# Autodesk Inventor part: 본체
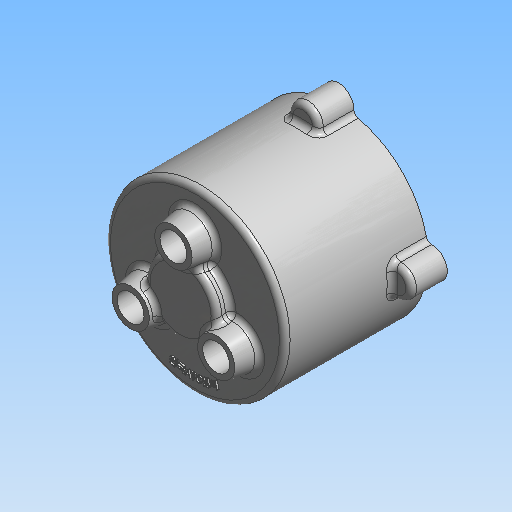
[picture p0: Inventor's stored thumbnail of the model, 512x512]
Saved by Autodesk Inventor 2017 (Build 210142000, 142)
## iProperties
Created: 2021-07
Part Number: 본체
Document SubType Name: 모델링
Designer: mdu
Material: 알루미늄 6061
Density: 2.71 g/cm^3
Mass: 473.469 g
Surface Area: 688.944 cm^2
Volume: 174.712 cm^3
Appearance: 알루미늄 - 평지
변환 표준: STEP AP214IS
파일 이름: C:\Users\SeoGD\Desktop\?쒗뿕\紐몄껜.stp
전처리기: Build: 253, Release: 2010 SP1 - Date: Wed 07/29/2009
전송 단위: 밀리미터
불확실성: 0.01
Author: mdu
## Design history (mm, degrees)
sketch "스케치2"
  geometry: C1 r 50 at (0, 0); 1 further point
  constraints: 1 centre point, 1 coincident
  dimensions: "d9" = 100 diameter of C1
extrude "돌출2" new body sketch "스케치2" distance "d10" = 80; taper "d11" = 0 deg
feature "쉘1" dims "d12" = 5
sketch "스케치3" dims "d13" = 55
  geometry: C1 r 7.5 at (0, 27.5); C2 r 12.5 at (0, 27.5); 2 further points
  constraints: 2 centre point, 2 coincident, 2 vertical alignment, 2 other
  dimensions: "d14" = 15 diameter of C1; "d15" = 25 diameter of C2
extrude "돌출3" join sketch "스케치3" distance "d16" = 12; taper "d17" = -10 deg
sketch "스케치4"
  geometry: L1 (0, 0)-(0, 88); L2 (0, 70)-(14, 70); L3 (-45, 75)-(45, 75) reference; L4 (-50, 80)-(50, 80) reference; L5 (14, 70)-(14, 75); L6 (20, 80)-(20, 88); L7 (20, 88)-(0, 88); L8 (20, 80)-(14, 75)
  constraints: 12 end point, 3 point on line, 2 perpendicular, 1 vertical
  dimensions: "d34" = 40 diameter of L6 L1; "d35" = 90 deg angle of L5 L3; "d36" = 5 distance between parallel lines of L2 L3; "d37" = 8 distance between parallel lines of L7 L4; "d51" = 28 diameter of L5.end L1
revolve "회전1" sketch "스케치4" stored, may be unused: angle "d38" = 90 deg
hole "구멍3" diameter "d41" = 15; stored, may be unused: countersink angle "d45" = 90 deg, drill point angle "d47" = 0 deg; dims "d39" = 10, "d40" = 10, "d42" = 6, "d43" = 22, "d44" = 13, "d46" = 15
chamfer "모따기2" distance "d48" = 1; stored, may be unused: second distance "d49" = 2, angle "d50" = 45 deg
fillet "모깎기4" dims "d78" = 3
hole "구멍2" diameter "d20" = 15; stored, may be unused: countersink angle "d24" = 90 deg, drill point angle "d26" = 118 deg; dims "d21" = 6, "d22" = 25, "d23" = 1, "d25" = 15, "d76" = 10, "d77" = 10
chamfer "모따기1" distance "d27" = 1; stored, may be unused: second distance "d28" = 2, angle "d29" = 45 deg
sketch "스케치9"
  geometry: C1 r 12.5 at (0, 0) reference; C2 r 12.5 at (-23.816, -41.25) reference; C3 r 12.5 at (23.816, -41.25) reference; 1 further point
extrude "돌출5" cut sketch "스케치9" stored distance "d79" = 10; taper "d80" = 0 deg
fillet "모깎기1" dims "d52" = 3
fillet "모깎기2" dims "d53" = 3, "d72" = 0.2
sketch "스케치5"
  geometry: A1 r 50 centre (0, 0) between (50, 0) and (-8.074, 49.344) reference; A2 r 8.5 centre (0, 52) between (8.074, 49.344) and (-8.074, 49.344); 1 further point
  constraints: 5 point on circle, 1 centre point, 1 horizontal alignment
  dimensions: "d54" = 90 deg dimension on point (0, 0) A2.centre A1.start; "d55" = 52 distance of A2.centre point (0, 0); "d56" = 17 diameter of A2
extrude "돌출4" join sketch "스케치5" distance "d57" = 20; taper "d58" = 0 deg
fillet "모깎기3" dims "d59" = 3
hole "구멍4" diameter "d62" = 4.134; stored, may be unused: countersink angle "d66" = 90 deg, drill point angle "d68" = 118 deg; dims "d60" = 10, "d61" = 10, "d63" = 12, "d64" = 22, "d65" = 13, "d67" = 15
sketch "스케치6"
  geometry: C1 r 47 at (0, 0) reference; C2 r 42.5 at (0, 0); 1 further point
  constraints: 1 centre point, 1 coincident, 1 other
  dimensions: "d73" = 85 diameter of C2
feature "엠보싱1" sketch "스케치6" dims "d34" = 40, "d35" = 90 deg, "d36" = 5, "d37" = 8, "d51" = 28, "d74" = 1, "d75" = 0
node "솔리드1"
node "솔리드 본체"
node "곡면 본체"
pattern_circular "원형 패턴1" dims angle "d31" = 360 deg
pattern_circular "원형 패턴2" dims angle "d70" = 360 deg
node "솔리드2"
